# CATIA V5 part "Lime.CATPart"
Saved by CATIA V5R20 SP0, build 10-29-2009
Part number: Lime
Bounding box of the stored display mesh (mm): x -40 to 5, y -17.5 to 17.5, z -10 to 10
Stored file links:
  C:\Users\thinkmotion1\Desktop\IAO OK\IAO_2010_1458_splanchena\Correction_Khaled\Lime.CATPart
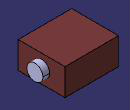
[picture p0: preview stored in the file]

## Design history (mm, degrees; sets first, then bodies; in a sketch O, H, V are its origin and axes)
Body1 (main body)
  Sketch1 on yz-plane, origin (0, 0, 0), H (0, 1, 0), V (0, 0, 1)
    line L1 (-17.5, -10) -> (17.5, -10)
    line L2 (17.5, -10) -> (17.5, 10)
    line L3 (17.5, 10) -> (-17.5, 10)
    line L4 (-17.5, 10) -> (-17.5, -10)
    distance H L1 = 10
    distance L1 L3 = 20
    length L3 = 35
    distance L2 V = 17.5
    horizontal: L1 H, L3 H
    vertical: L2 V, L4 V
  Pad1: profile Sketch1, direction (-1, 0, 0), length 40
  Sketch2 on yz-plane, origin (0, 0, 0), H (0, 1, 0), V (0, 0, 1)
    circle A1 centre (0, 0) radius 6
    radius A1 = 6
  Pad2: profile Sketch2, direction (1, 0, 0), length 5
